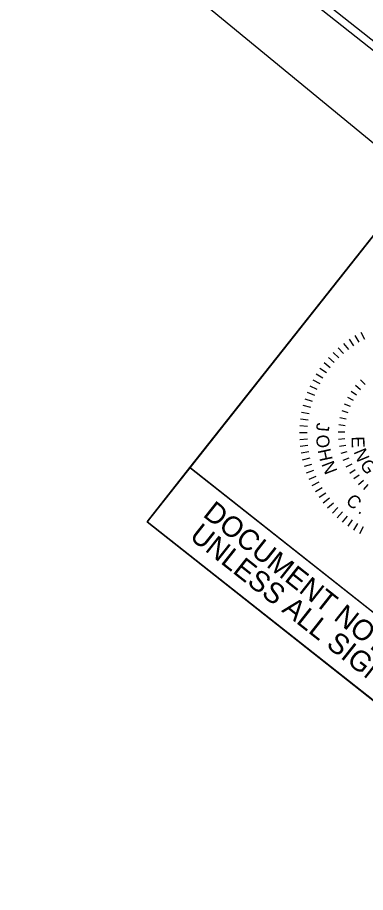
# Model space of a CAD drawing. Extents: x 557005 to 559009, y 505746 to 507841.
# Drawn here: x 558671 to 558789.4, y 506648.8 to 506946.8 of the extents above; entities that cross this region are included whole.
import ezdxf

# ---------------------------------------------------------------- set-up
doc = ezdxf.new("R2010")
doc.units = 0
for name, color, linetype in [('Old_Level_21', 7, 'Continuous'), ('Scratch_Level_5', 7, 'Continuous'), ('Sheet Border Standard 30in CELL', 7, 'Continuous'), ('Sheet Plot Border Inside CELL', 7, 'Continuous'), ('Sheet Sticker Exception Certification CELL', 7, 'Continuous')]:
    doc.layers.add(name, color=color, linetype=linetype)

msp = doc.modelspace()

# ---------------------------------------------------------------- linework, layer by layer
at = {"layer": 'Old_Level_21'}
for p, q in [((558787.89, 506839.57), (558789.1, 506837.23)), ((558783.87, 506837.19), (558785.36, 506835)), ((558785.84, 506838.44), (558787.19, 506836.17)), ((558780.18, 506834.32), (558781.92, 506832.34)), ((558781.98, 506835.81), (558783.6, 506833.73)), ((558776.86, 506831.04), (558778.82, 506829.28)), ((558778.47, 506832.73), (558780.32, 506830.86)), ((558773.95, 506827.38), (558776.11, 506825.87)), ((558775.35, 506829.25), (558777.42, 506827.62)), ((558772.68, 506825.42), (558774.92, 506824.05)), ((558771.51, 506823.4), (558773.84, 506822.16)), ((558786.07, 506821.54), (558787.76, 506820.13)), ((558787.74, 506823.35), (558789.28, 506821.79)), ((558769.57, 506819.15), (558772.03, 506818.2)), ((558770.48, 506821.3), (558772.88, 506820.2)), ((558784.59, 506819.57), (558786.4, 506818.33)), ((558768.8, 506816.95), (558771.31, 506816.15)), ((558783.3, 506817.47), (558785.23, 506816.42)), ((558767.65, 506812.42), (558770.24, 506811.92)), ((558768.16, 506814.7), (558770.71, 506814.05)), ((558781.36, 506812.94), (558783.46, 506812.28)), ((558782.22, 506815.25), (558784.24, 506814.39)), ((558767.29, 506810.11), (558769.9, 506809.78)), ((558780.74, 506810.56), (558782.88, 506810.11)), ((558767.06, 506807.78), (558769.69, 506807.61)), ((558780.33, 506808.14), (558782.51, 506807.88)), ((558766.98, 506805.45), (558769.61, 506805.43)), ((558780.17, 506805.68), (558782.37, 506805.64)), ((558767.04, 506803.11), (558769.67, 506803.25)), ((558767.23, 506800.78), (558769.85, 506801.08)), ((558780.25, 506803.21), (558782.43, 506803.39)), ((558780.56, 506800.77), (558782.72, 506801.15)), ((558767.57, 506798.47), (558770.17, 506798.93)), ((558781.1, 506798.37), (558783.22, 506798.96)), ((558768.05, 506796.18), (558770.61, 506796.8)), ((558768.66, 506793.93), (558771.18, 506794.7)), ((558781.88, 506796.03), (558783.93, 506796.82)), ((558782.88, 506793.78), (558784.84, 506794.77)), ((558769.41, 506791.72), (558771.88, 506792.63)), ((558784.09, 506791.63), (558785.95, 506792.8)), ((558770.29, 506789.55), (558772.7, 506790.62)), ((558771.31, 506787.44), (558773.64, 506788.66)), ((558787.23, 506790.97), (558785.49, 506789.62)), ((558787.1, 506787.74), (558788.7, 506789.25)), ((558772.44, 506785.4), (558774.71, 506786.75)), ((558788.87, 506786.03), (558790.32, 506787.69)), ((558773.69, 506783.43), (558775.88, 506784.92)), ((558775.07, 506781.54), (558777.15, 506783.16)), ((558776.56, 506779.74), (558778.54, 506781.47)), ((558778.15, 506778.03), (558780.02, 506779.88)), ((558779.84, 506776.42), (558781.6, 506778.38)), ((558781.63, 506774.91), (558783.26, 506776.98)), ((558783.5, 506773.51), (558785.01, 506775.67)), ((558785.46, 506772.23), (558786.83, 506774.48)), ((558787.48, 506771.07), (558788.72, 506773.4))]:
    msp.add_line(p, q, dxfattribs=at)
at = {"layer": 'Scratch_Level_5'}
msp.add_lwpolyline([(558502.21, 506199.86), (558069.07, 506542.35), (558000.13, 506451.2), (557930.66, 506511.32), (557889.73, 506539.36), (557425.46, 506933.59), (557393.31, 506960), (557371.36, 506969.71), (557385.34, 506999.14), (557443.19, 507138.35), (557378.87, 507175.51), (557803.85, 507716.87), (558807.23, 506891.56), (558715.12, 506775.08), (558872.03, 506651.01)], close=True, dxfattribs=at)
at = {"layer": 'Sheet Border Standard 30in CELL'}
for points in [[(558979.69, 506787.13), (557803.06, 507717.49), (557151.81, 506893.85), (558328.44, 505963.5)], [(558799.47, 506881.76), (558877.95, 506819.7), (558808.18, 506731.46), (558729.7, 506793.51)]]:
    msp.add_lwpolyline(points, close=True, dxfattribs=at)
at = {"layer": 'Sheet Plot Border Inside CELL'}
msp.add_lwpolyline([(558991.07, 506781.38), (557683.84, 507815), (557029.43, 506987.37), (558336.66, 505953.74)], close=True, dxfattribs=at)
at = {"layer": 'Sheet Sticker Exception Certification CELL'}
for p, q in [((558715.12, 506775.08), (558729.7, 506793.51)), ((558729.7, 506793.51), (558886.61, 506669.44)), ((558872.03, 506651.01), (558715.12, 506775.08))]:
    msp.add_line(p, q, dxfattribs=at)

# ---------------------------------------------------------------- texts
at = {"layer": 'Old_Level_21'}
for s, rotation, p in [('J', 265.5218, (558772.84, 506808.87)), ('O', 273.5937, (558772.63, 506804.57)), ('E', 271.6569, (558784.66, 506804.07)), ('H', 282.2364, (558773.14, 506799.44)), ('N', 292.512, (558785.28, 506798.91)), ('N', 290.909, (558774.35, 506794.7)), ('G', 301.2782, (558787.37, 506794.63)), ('C', 317.6768, (558782.44, 506781.73)), ('.', 325.4191, (558786.64, 506778.24))]:
    msp.add_text(s, height=4.39, rotation=rotation, dxfattribs=at).set_placement(p)
at = {"layer": 'Sheet Sticker Exception Certification CELL'}
for s, p in [('DOCUMENT NOT CONSIDERED FINAL', (558733.79, 506777.09)), ('UNLESS ALL SIGNATURES COMPLETED', (558729.21, 506769.49))]:
    msp.add_text(s, height=7, rotation=321.6667, dxfattribs=at).set_placement(p)

doc.saveas('drawing.dxf')
